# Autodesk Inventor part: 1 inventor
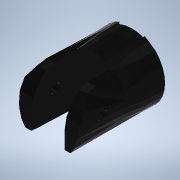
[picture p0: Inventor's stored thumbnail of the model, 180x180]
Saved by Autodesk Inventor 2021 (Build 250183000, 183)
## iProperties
Created: 2022-10
Part Number: 1 inventor
Material: Genérico
Document SubType Name: Modeling
Designer: Yair Obed
Density: 1 g/cm^3
Appearance: Valor por defecto
Author: Yair Obed
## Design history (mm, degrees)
node "1"
  node "MeshFeature1"
